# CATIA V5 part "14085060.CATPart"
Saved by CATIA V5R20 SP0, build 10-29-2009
Part number: 14085060
Definition: NONE
Nomenclature: 14085060
Source: Unknown
Description: 14085060
Bounding box of the stored display mesh (mm): x -30 to 120, y -56.5 to 46.401, z -46.6 to 46.6
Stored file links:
  C:\Users\Utente\Desktop\IO LAVORO\3D X SITO CF\X SITO\PLASTICA\RF2\14085060.CATPart
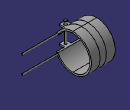
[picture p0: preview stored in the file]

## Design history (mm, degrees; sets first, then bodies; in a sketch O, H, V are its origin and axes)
Body1 "14085060" (main body)
  Solid1: solid without history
